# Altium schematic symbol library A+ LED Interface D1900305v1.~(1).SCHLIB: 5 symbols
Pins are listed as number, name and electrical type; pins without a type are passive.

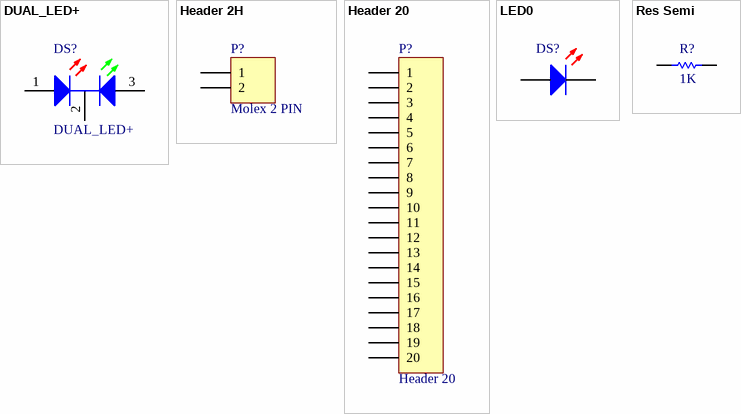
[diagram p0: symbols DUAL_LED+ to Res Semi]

## DUAL_LED+
designator DS?
Green, Red  LED Indication - Discrete 2.2V Green, 2V Red Radial - 3 Leads; Manufacturer: Lumex; Manufacturer Part Number: SSL-LX3059IGW; Description: LUMEX - SSL-LX3059IGW - LED, 3MM, RED/GREEN, 30MCD; Lens Color: White; Viewing Angle: 60°; Test Current: 20mA; Lens Style: Dome,Round,Diffused,Colorless; Luminous Intensity: 30mcd; Lens Transparency: Diffused; Dominant Wavelength: 635nm; Forward Current: 150mA; Power Dissipation: 105mW; Wavelength: 565nm; Number of LEDs: 2
footprint COM_CATHODE LED
pins: 1 A, 2 K, 3 A

## Header 2H
designator P?, comment Molex 2 PIN
Header, 2-Pin, Right Angle; Description: MOLEX - 22-11-2022 - CONNECTOR, HEADER, 2POS, 1ROW, 2.54MM; Number of Positions: 2; Gender: Male; Contact Resistance: 10mR; Current Rating: 4A; Voltage Rating: 250V; Max Current Rating: 7A; Insulation Resistance: 50GR; Pitch: 2.54mm; Approvals: UL,CSA
signal-integrity model Connector
footprint 2Pin_Molex 100 mil
pins: 1, 2

## Header 20
designator P?
Header, 20-Pin; Manufacturer: Amphenol FCI; Manufacturer Part Number: 71918-120LF; Description: CONN HEADER VERT 20POS 2.54MM; Current Rating: 1A; Mating Cycles: 250; Number of Poles: 20; Voltage Rating: 1.5kV; Insulation Resistance: 100GR; Gender: Male; Connector Type: Male Pin; Pitch: 2.54mm; Contact Post Length: 2.9mm; Row Spacing: 0.1inch; Hole Diameter: 1mm; Approvals: UL,CSA
signal-integrity model Connector
footprint IDC 20 _Vertical
pins: 1, 2, 3, 4, 5, 6, 7, 8, 9, 10, 11, 12, 13, 14, 15, 16, 17, 18, 19, 20

## LED0
designator DS?  (value not drawn)
Red 640nm LED Indication - Discrete 1.85V Radial; Manufacturer: Kingbright; Manufacturer Part Number: WP710A10SRD/F; Description: LED RED DIFFUSED T-1 T/H; Forward Current: 20mA; Luminous Intensity: 160mcd; Lens Style: Dome,Diffused; Viewing Angle: 40°; Lens Transparency: Diffused
simulation model LED0 (Diode)
footprint RED_led
pins: 1 A, 2 K

## Res Semi
designator R?, comment 1K
Semiconductor Resistor; Manufacturer: Panasonic; Manufacturer Part Number: ERJ-8ENF1001V; Description: RES SMD 1K OHM 1% 1/4W 1206; Resistance: 1kR; Tolerance: 1%; Voltage Rating: 200V; Power Rating: 250mW; Temperature Coefficient: 100ppm/°C
simulation model RES (Semiconductor Resistor)
signal-integrity model Res Semi
footprint 3216[1206] (Chip Resistor; Body 3.2 x 1.6 mm (LxW typ))
pins: 1, 2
